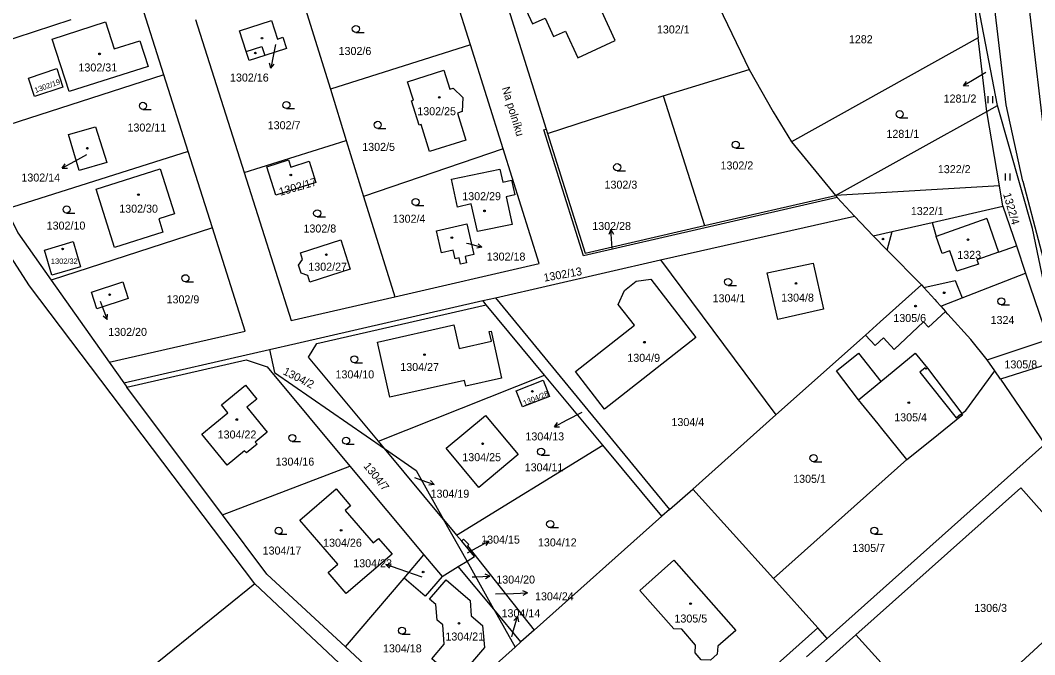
# Model space of a CAD drawing. Extents: x -724107 to -720612, y -1045267 to -1038441.
# Drawn here: x -722495.8 to -722280.4, y -1043826.7 to -1043692 of the extents above; entities that cross this region are included whole.
import ezdxf

# ---------------------------------------------------------------- set-up
doc = ezdxf.new("R2010")
doc.units = 0
for name, color, linetype in [('Hranice parcel', 7, 'Continuous'), ('Parcelní čísla', 7, 'Continuous'), ('Pop  PČ popisy', 7, 'Continuous'), ('Vnitřní kresba', 7, 'Continuous'), ('Značky budov', 7, 'Continuous'), ('Značky kultur', 7, 'Continuous')]:
    doc.layers.add(name, color=color, linetype=linetype)

msp = doc.modelspace()

# ---------------------------------------------------------------- linework, layer by layer
at = {"layer": 'Hranice parcel'}
for p, q in [((-722399.97, -1043664.64), (-722384.11, -1043715.14)), ((-722294.31, -1043678.85), (-722292.37, -1043695.73)), ((-722400.2, -1043697.26), (-722405.73, -1043679.7)), ((-722436.75, -1043684.63), (-722429.94, -1043706.64)), ((-722349.01, -1043685.75), (-722340.98, -1043702.46)), ((-722465.29, -1043703.63), (-722470.49, -1043687.27)), ((-722485.03, -1043691.96), (-722513.89, -1043701.27)), ((-722458.59, -1043691.86), (-722448.26, -1043724.35)), ((-722292.37, -1043695.73), (-722332.05, -1043717.8)), ((-722290.57, -1043711.4), (-722292.37, -1043695.73)), ((-722400.2, -1043697.26), (-722429.94, -1043706.64)), ((-722393.26, -1043719.34), (-722400.2, -1043697.26)), ((-722359.26, -1043708.03), (-722340.98, -1043702.46)), ((-722465.29, -1043703.63), (-722506.29, -1043716.77)), ((-722460.15, -1043719.85), (-722465.29, -1043703.63)), ((-722429.94, -1043706.64), (-722426.56, -1043717.55)), ((-722383.81, -1043716.09), (-722359.26, -1043708.03)), ((-722359.26, -1043708.03), (-722350.49, -1043735.62)), ((-722322.69, -1043729.23), (-722290.57, -1043711.4)), ((-722290.57, -1043711.4), (-722288.3, -1043710.14)), ((-722287.85, -1043727.2), (-722290.57, -1043711.4)), ((-722384.11, -1043715.14), (-722383.81, -1043716.09)), ((-722448.26, -1043724.35), (-722426.56, -1043717.55)), ((-722426.56, -1043717.55), (-722422.87, -1043729.46)), ((-722332.05, -1043717.8), (-722322.69, -1043729.23)), ((-722460.15, -1043719.85), (-722498.76, -1043732.14)), ((-722454.98, -1043736.06), (-722460.15, -1043719.85)), ((-722393.26, -1043719.34), (-722422.87, -1043729.46)), ((-722287.85, -1043727.2), (-722322.69, -1043729.23)), ((-722287.12, -1043731.47), (-722287.85, -1043727.2)), ((-722422.87, -1043729.46), (-722416.28, -1043750.74)), ((-722350.49, -1043735.62), (-722322.69, -1043729.23)), ((-722322.69, -1043729.23), (-722322.3, -1043729.65)), ((-722318.63, -1043733.59), (-722322.3, -1043729.65)), ((-722359.86, -1043742.91), (-722318.63, -1043733.59)), ((-722314.67, -1043737.81), (-722318.63, -1043733.59)), ((-722454.98, -1043736.06), (-722489.2, -1043747.21)), ((-722394.9, -1043750.94), (-722359.86, -1043742.91)), ((-722359.86, -1043742.91), (-722335.35, -1043775.77)), ((-722282.31, -1043745.68), (-722277.54, -1043759.8)), ((-722489.2, -1043747.21), (-722476.9, -1043764.62)), ((-722397.53, -1043751.54), (-722394.9, -1043750.94)), ((-722396.82, -1043752.4), (-722397.53, -1043751.54)), ((-722384.5, -1043767.37), (-722396.82, -1043752.4)), ((-722394.9, -1043750.94), (-722357.94, -1043795.88)), ((-722300.32, -1043752.74), (-722299.29, -1043753.88)), ((-722335.35, -1043775.77), (-722316.32, -1043758.85)), ((-722290.43, -1043764.1), (-722277.54, -1043759.8)), ((-722473.79, -1043769.01), (-722442.89, -1043761.93)), ((-722476.9, -1043764.62), (-722473.79, -1043769.01)), ((-722288.82, -1043766.47), (-722290.43, -1043764.1)), ((-722419.72, -1043781.41), (-722384.5, -1043767.37)), ((-722372.07, -1043782.26), (-722384.5, -1043767.37)), ((-722287.62, -1043768.22), (-722288.82, -1043766.47)), ((-722473.79, -1043769.01), (-722473.14, -1043769.88)), ((-722452.82, -1043797.04), (-722473.14, -1043769.88)), ((-722352.97, -1043791.54), (-722335.35, -1043775.77)), ((-722418.43, -1043782.96), (-722419.72, -1043781.41)), ((-722403.13, -1043801.3), (-722372.07, -1043782.26)), ((-722359.53, -1043797.29), (-722372.07, -1043782.26)), ((-722405.89, -1043798), (-722418.43, -1043782.96)), ((-722452.82, -1043797.04), (-722425.78, -1043786.68)), ((-722425.78, -1043786.68), (-722410.07, -1043805.52)), ((-722335.87, -1043810.55), (-722307.55, -1043785.3)), ((-722357.94, -1043795.88), (-722352.97, -1043791.54)), ((-722352.97, -1043791.54), (-722335.87, -1043810.55)), ((-722405.89, -1043798), (-722403.13, -1043801.3)), ((-722400.92, -1043806.87), (-722405.89, -1043798)), ((-722359.53, -1043797.29), (-722386.68, -1043821.48)), ((-722357.94, -1043795.88), (-722359.53, -1043797.29)), ((-722403.13, -1043801.3), (-722402.04, -1043802.6)), ((-722414.27, -1043810.44), (-722410.07, -1043805.52)), ((-722410.07, -1043805.52), (-722406.23, -1043810.12)), ((-722406.23, -1043810.12), (-722402.77, -1043808)), ((-722402.77, -1043808), (-722400.92, -1043806.87)), ((-722395.23, -1043817.04), (-722402.77, -1043808)), ((-722395.23, -1043817.04), (-722400.92, -1043806.87)), ((-722426.72, -1043825.03), (-722414.27, -1043810.44)), ((-722326.45, -1043821.03), (-722335.87, -1043810.55)), ((-722426.92, -1043829.6), (-722445.95, -1043811.69)), ((-722389.46, -1043823.95), (-722395.23, -1043817.04)), ((-722395.23, -1043817.04), (-722390.73, -1043825.08)), ((-722386.68, -1043821.48), (-722389.46, -1043823.95)), ((-722376.61, -1043865.6), (-722326.45, -1043821.03)), ((-722324.44, -1043823.26), (-722326.45, -1043821.03)), ((-722328.83, -1043827.18), (-722324.44, -1043823.26)), ((-722408.93, -1043841.47), (-722426.72, -1043825.03)), ((-722390.73, -1043825.08), (-722408.93, -1043841.47)), ((-722389.46, -1043823.95), (-722390.73, -1043825.08))]:
    msp.add_line(p, q, dxfattribs=at)
for points in [[(-722389.81, -1043682.03), (-722387.9, -1043686.15), (-722389.71, -1043686.9), (-722386.99, -1043692.79), (-722384.34, -1043691.6), (-722382.56, -1043695.47), (-722380.02, -1043694.33), (-722377.41, -1043699.97), (-722369.45, -1043696.29), (-722378.83, -1043675.95), (-722382.58, -1043668.42), (-722385.33, -1043669.59), (-722392.46, -1043672.62), (-722390.91, -1043676.37), (-722389.81, -1043682.03)], [(-722288.3, -1043710.14), (-722291.19, -1043695.07), (-722294.31, -1043678.85)], [(-722489.03, -1043696.02), (-722477.66, -1043692.38), (-722475.83, -1043698.09), (-722470.41, -1043696.36), (-722468.65, -1043701.83), (-722485.43, -1043707.16), (-722489.03, -1043696.02)], [(-722447.81, -1043698.64), (-722449.2, -1043694.24), (-722442.42, -1043692.09), (-722441.18, -1043696.01), (-722440.03, -1043695.64), (-722439.27, -1043698.03), (-722443.85, -1043699.49), (-722447.2, -1043700.55), (-722447.81, -1043698.64)], [(-722445.95, -1043811.69), (-722493.86, -1043748.42), (-722499.71, -1043739.26), (-722517.12, -1043702.29)], [(-722486.76, -1043706.23), (-722492.79, -1043708.22), (-722494.05, -1043704.29), (-722488.03, -1043702.26), (-722486.76, -1043706.23)], [(-722403.85, -1043706.43), (-722401.79, -1043708.4), (-722401.97, -1043711.4), (-722402.97, -1043711.72), (-722401.16, -1043717.45), (-722408.86, -1043719.89), (-722410.68, -1043714.14), (-722411.07, -1043714.26), (-722412.7, -1043709.12), (-722412.3, -1043708.99), (-722413.54, -1043705.06), (-722405.86, -1043702.62), (-722404.54, -1043706.64), (-722403.85, -1043706.43)], [(-722340.98, -1043702.46), (-722335.9, -1043711.44), (-722332.05, -1043717.8)], [(-722275.1, -1043763.67), (-722280.81, -1043736.21), (-722288.3, -1043710.14)], [(-722477.39, -1043722.2), (-722483.25, -1043723.88), (-722485.57, -1043716.24), (-722479.8, -1043714.65), (-722477.39, -1043722.2)], [(-722322.3, -1043729.65), (-722350.38, -1043736.11), (-722376.19, -1043742.04), (-722384.58, -1043715.29), (-722384.11, -1043715.14)], [(-722383.81, -1043716.09), (-722375.85, -1043741.45), (-722350.49, -1043735.62)], [(-722416.28, -1043750.74), (-722385.6, -1043743.69), (-722393.26, -1043719.34)], [(-722434.44, -1043721.95), (-722433.02, -1043726.43), (-722441.5, -1043729.12), (-722443.41, -1043723.12), (-722438.83, -1043721.67), (-722438.35, -1043723.19), (-722434.44, -1043721.95)], [(-722479.7, -1043727.86), (-722466.08, -1043723.56), (-722463.07, -1043733.1), (-722466.36, -1043734.15), (-722465.49, -1043737.01), (-722475.76, -1043740.27), (-722479.7, -1043727.86)], [(-722448.26, -1043724.35), (-722438.27, -1043755.79), (-722416.28, -1043750.74)], [(-722404.21, -1043725.77), (-722393.98, -1043723.6), (-722393.34, -1043726.39), (-722391.5, -1043725.97), (-722390.74, -1043729.07), (-722392.63, -1043729.51), (-722391.34, -1043735.36), (-722398.71, -1043736.86), (-722400.01, -1043731.01), (-722402.97, -1043731.67), (-722404.21, -1043725.77)], [(-722498.76, -1043732.14), (-722496.3, -1043737.16), (-722489.2, -1043747.21)], [(-722314.67, -1043737.81), (-722310.66, -1043736.89), (-722306.56, -1043735.94), (-722302.18, -1043734.94), (-722287.12, -1043731.47)], [(-722287.12, -1043731.47), (-722284.27, -1043739.9), (-722282.31, -1043745.68)], [(-722406.33, -1043741.37), (-722407.4, -1043736.69), (-722400.97, -1043735.22), (-722399.47, -1043741.75), (-722401.32, -1043742.17), (-722401.01, -1043743.54), (-722402.28, -1043743.83), (-722402.59, -1043742.46), (-722403.47, -1043742.66), (-722403.89, -1043740.81), (-722406.33, -1043741.37)], [(-722476.9, -1043764.62), (-722448.02, -1043758.03), (-722454.98, -1043736.06)], [(-722482.98, -1043744.34), (-722489.07, -1043746.13), (-722490.63, -1043740.82), (-722484.59, -1043738.98), (-722482.98, -1043744.34)], [(-722434.28, -1043747.64), (-722434.74, -1043746.23), (-722436.14, -1043745.72), (-722436.7, -1043744.02), (-722435.85, -1043742.79), (-722436.3, -1043741.38), (-722427.75, -1043738.6), (-722425.7, -1043744.89), (-722434.28, -1043747.64)], [(-722304.4, -1043748.21), (-722311.69, -1043740.83), (-722314.67, -1043737.81)], [(-722327.44, -1043743.57), (-722325.2, -1043753.37), (-722334.92, -1043755.57), (-722337.15, -1043745.65), (-722327.44, -1043743.57)], [(-722300.32, -1043752.74), (-722295.78, -1043750.96), (-722282.31, -1043745.68)], [(-722472.85, -1043751.06), (-722479.52, -1043753.28), (-722480.69, -1043749.75), (-722474.02, -1043747.53), (-722472.85, -1043751.06)], [(-722368.79, -1043752.33), (-722367.51, -1043749.37), (-722365.03, -1043747.38), (-722361.89, -1043746.97), (-722352.3, -1043759.4), (-722371.72, -1043774.58), (-722377.91, -1043766.61), (-722365.35, -1043756.78), (-722368.79, -1043752.33)], [(-722316.32, -1043758.85), (-722313.19, -1043756.06), (-722311.22, -1043754.29), (-722304.4, -1043748.21)], [(-722304.4, -1043748.21), (-722303.93, -1043748.73), (-722301.59, -1043751.33), (-722301.25, -1043751.7), (-722300.32, -1043752.74)], [(-722442.89, -1043761.93), (-722437.26, -1043760.64), (-722397.53, -1043751.54)], [(-722419.72, -1043781.41), (-722434.61, -1043763.57), (-722432.81, -1043760.65), (-722396.82, -1043752.4)], [(-722299.29, -1043753.88), (-722302.93, -1043757.15), (-722303.95, -1043756.01), (-722310.18, -1043761.89), (-722312.46, -1043759.47), (-722314.25, -1043761.09), (-722316.32, -1043758.85)], [(-722290.43, -1043764.1), (-722293.91, -1043759.78), (-722298.79, -1043754.44), (-722299.29, -1043753.88)], [(-722393.58, -1043767.97), (-722401.2, -1043769.7), (-722401.48, -1043768.48), (-722417.31, -1043772.04), (-722419.94, -1043760.35), (-722403.74, -1043756.71), (-722402.6, -1043761.7), (-722395.75, -1043760.14), (-722396.2, -1043758.12), (-722395.82, -1043758.02), (-722393.58, -1043767.97)], [(-722277.54, -1043759.8), (-722276.02, -1043764.56), (-722287.62, -1043768.22)], [(-722442.89, -1043761.93), (-722441.77, -1043766.8), (-722418.43, -1043782.96)], [(-722307.55, -1043785.3), (-722312.8, -1043778.68), (-722313.61, -1043777.7), (-722317.81, -1043772.61), (-722322.46, -1043766.44), (-722317.76, -1043762.71), (-722313.06, -1043768.7), (-722305.78, -1043762.69), (-722303.17, -1043765.87), (-722295.87, -1043775.49)], [(-722473.14, -1043769.88), (-722447.84, -1043764.09), (-722443.38, -1043765.59), (-722425.78, -1043786.68)], [(-722295.87, -1043775.49), (-722295.02, -1043774.86), (-722288.82, -1043766.47)], [(-722447.68, -1043774.16), (-722443.35, -1043779.49), (-722445.89, -1043781.57), (-722445.51, -1043782.04), (-722447.76, -1043783.88), (-722448.14, -1043783.41), (-722451.85, -1043786.45), (-722457.23, -1043779.88), (-722451.7, -1043775.33), (-722453.06, -1043773.68), (-722447.96, -1043769.48), (-722445.55, -1043772.46), (-722447.68, -1043774.16)], [(-722384.74, -1043768.46), (-722383.41, -1043771.87), (-722389.14, -1043774.12), (-722390.45, -1043770.71), (-722384.74, -1043768.46)], [(-722287.62, -1043768.22), (-722278.2, -1043782.03), (-722324.44, -1043823.26)], [(-722405.36, -1043782.87), (-722397.03, -1043775.9), (-722390.05, -1043784.23), (-722398.38, -1043791.21), (-722405.36, -1043782.87)], [(-722307.55, -1043785.3), (-722301.92, -1043780.78), (-722295.89, -1043775.95), (-722295.66, -1043775.76), (-722295.87, -1043775.49)], [(-722418.43, -1043782.96), (-722411.69, -1043787.63), (-722405.89, -1043798)], [(-722430.43, -1043809.24), (-722428.38, -1043807.47), (-722436.43, -1043798.17), (-722428.71, -1043791.53), (-722425.65, -1043795.1), (-722426.78, -1043796.08), (-722420.84, -1043802.99), (-722419.7, -1043802.01), (-722416.82, -1043805.35), (-722426.56, -1043813.71), (-722430.43, -1043809.24)], [(-722267.34, -1043800.47), (-722271.69, -1043804.36), (-722283.34, -1043791.3), (-722318.33, -1043822.49)], [(-722426.72, -1043825.03), (-722443.43, -1043809.58), (-722452.82, -1043797.04)], [(-722402.04, -1043802.6), (-722401.94, -1043802.5), (-722401.67, -1043802.21), (-722400.53, -1043803.28), (-722400.8, -1043803.57), (-722386.68, -1043821.48)], [(-722400.92, -1043806.87), (-722399.31, -1043805.88), (-722402.04, -1043802.6)], [(-722357.03, -1043806.67), (-722343.87, -1043821.55), (-722347.67, -1043824.9), (-722347.8, -1043826.6), (-722349.22, -1043827.88), (-722351.19, -1043827.79), (-722352.46, -1043826.3), (-722352.37, -1043824.66), (-722355.27, -1043821.32), (-722357.01, -1043821.22), (-722364.19, -1043813.05), (-722357.03, -1043806.67)], [(-722406.23, -1043810.12), (-722409.8, -1043814.26), (-722414.27, -1043810.44)], [(-722405.38, -1043810.82), (-722400.26, -1043815.19), (-722400.01, -1043818.46), (-722397.63, -1043820.51), (-722397.22, -1043825.16), (-722403.68, -1043832.66), (-722405.81, -1043830.85), (-722405.92, -1043829.72), (-722408.42, -1043827.57), (-722405.77, -1043824.45), (-722406.09, -1043820.38), (-722407.29, -1043819.35), (-722407.54, -1043816.06), (-722408.88, -1043814.91), (-722405.38, -1043810.82)], [(-722445.95, -1043811.69), (-722477.48, -1043837.14), (-722474.95, -1043859.15)], [(-722266.76, -1043839.14), (-722271.42, -1043834.28), (-722265.86, -1043829.16), (-722274.28, -1043820.01), (-722299.56, -1043843.28), (-722318.33, -1043822.49)], [(-722318.33, -1043822.49), (-722323.78, -1043827.41), (-722326.46, -1043829.83)]]:
    msp.add_lwpolyline(points, dxfattribs=at)
at = {"layer": 'Pop  PČ popisy'}
for p, q in [((-722441.58, -1043697.18), (-722441.99, -1043699.26)), ((-722441.99, -1043699.26), (-722442.56, -1043702.21)), ((-722442.56, -1043702.21), (-722442.86, -1043701.13)), ((-722442.56, -1043702.21), (-722441.88, -1043701.32)), ((-722290.77, -1043703.13), (-722292.89, -1043704.41)), ((-722292.89, -1043704.41), (-722295.46, -1043705.96)), ((-722295.46, -1043705.96), (-722294.86, -1043705.01)), ((-722295.46, -1043705.96), (-722294.35, -1043705.87)), ((-722484.24, -1043721.98), (-722486.86, -1043723.44)), ((-722486.86, -1043723.44), (-722486.23, -1043722.51)), ((-722481.75, -1043720.6), (-722484.24, -1043721.98)), ((-722486.86, -1043723.44), (-722485.75, -1043723.39)), ((-722370.36, -1043736.45), (-722370.79, -1043737.48)), ((-722370.15, -1043739.44), (-722370.36, -1043736.45)), ((-722370.36, -1043736.45), (-722369.79, -1043737.41)), ((-722401, -1043739.33), (-722400.64, -1043739.43)), ((-722400.64, -1043739.43), (-722397.74, -1043740.21)), ((-722397.74, -1043740.21), (-722398.58, -1043739.46)), ((-722370.08, -1043740.39), (-722370.15, -1043739.44)), ((-722397.74, -1043740.21), (-722398.84, -1043740.43)), ((-722478.84, -1043751.65), (-722478.41, -1043752.76)), ((-722478.41, -1043752.76), (-722477.33, -1043755.56)), ((-722477.33, -1043755.56), (-722478.16, -1043754.81)), ((-722477.33, -1043755.56), (-722477.23, -1043754.45)), ((-722376.52, -1043775.27), (-722379.72, -1043776.94)), ((-722379.72, -1043776.94), (-722382.37, -1043778.35)), ((-722382.37, -1043778.35), (-722381.72, -1043777.44)), ((-722382.37, -1043778.35), (-722381.25, -1043778.32)), ((-722412.08, -1043789.12), (-722410.76, -1043789.58)), ((-722410.76, -1043789.58), (-722407.92, -1043790.56)), ((-722407.92, -1043790.56), (-722409.03, -1043790.7)), ((-722407.92, -1043790.56), (-722408.71, -1043789.76)), ((-722400.82, -1043805.07), (-722398.94, -1043804.05)), ((-722398.94, -1043804.05), (-722396.29, -1043802.64)), ((-722396.29, -1043802.64), (-722397.41, -1043802.67)), ((-722396.29, -1043802.64), (-722396.94, -1043803.55)), ((-722418.13, -1043807.53), (-722417.02, -1043807.41)), ((-722415.31, -1043808.56), (-722418.13, -1043807.53)), ((-722418.13, -1043807.53), (-722417.36, -1043808.35)), ((-722410.48, -1043810.27), (-722415.31, -1043808.56)), ((-722399.84, -1043810.2), (-722399.05, -1043810.17)), ((-722399.05, -1043810.17), (-722396.05, -1043810.07)), ((-722396.05, -1043810.07), (-722397.07, -1043809.6)), ((-722396.05, -1043810.07), (-722397.03, -1043810.6)), ((-722394.89, -1043813.8), (-722391.08, -1043813.7)), ((-722391.08, -1043813.7), (-722388.08, -1043813.59)), ((-722388.08, -1043813.59), (-722389.1, -1043813.13)), ((-722388.08, -1043813.59), (-722389.06, -1043814.13)), ((-722391.02, -1043821.51), (-722390.19, -1043818.62)), ((-722390.19, -1043818.62), (-722390.95, -1043819.45)), ((-722390.19, -1043818.62), (-722389.99, -1043819.73)), ((-722391.42, -1043822.9), (-722391.02, -1043821.51))]:
    msp.add_line(p, q, dxfattribs=at)
at = {"layer": 'Vnitřní kresba'}
for p, q in [((-722286.43, -1043710), (-722300.29, -1043591.22)), ((-722277.74, -1043721.43), (-722293.12, -1043591.36)), ((-722447.81, -1043698.64), (-722444.46, -1043697.57)), ((-722444.46, -1043697.57), (-722443.85, -1043699.49)), ((-722282.86, -1043726.17), (-722286.43, -1043710)), ((-722282.86, -1043726.17), (-722275.66, -1043753.66)), ((-722302.18, -1043734.94), (-722301.32, -1043737.92)), ((-722290.55, -1043734.13), (-722301.32, -1043737.92)), ((-722290.55, -1043734.13), (-722288.07, -1043741.24)), ((-722311.69, -1043740.83), (-722310.66, -1043736.89)), ((-722300.03, -1043741.52), (-722301.32, -1043737.92)), ((-722298.38, -1043740.97), (-722300.03, -1043741.52)), ((-722296.93, -1043745.3), (-722298.38, -1043740.97)), ((-722288.07, -1043741.24), (-722292.66, -1043742.87)), ((-722288.07, -1043741.24), (-722284.27, -1043739.9)), ((-722292.34, -1043743.77), (-722296.93, -1043745.3)), ((-722292.66, -1043742.87), (-722292.34, -1043743.77)), ((-722303.93, -1043748.73), (-722297.23, -1043747.27)), ((-722297.23, -1043747.27), (-722295.78, -1043750.96)), ((-722303.63, -1043765.79), (-722304.78, -1043766.74)), ((-722304.78, -1043766.74), (-722297.08, -1043776.44)), ((-722303.4, -1043766.06), (-722303.63, -1043765.79)), ((-722303.17, -1043765.87), (-722303.4, -1043766.06)), ((-722317.81, -1043772.61), (-722313.06, -1043768.7)), ((-722297.08, -1043776.44), (-722296.11, -1043775.67)), ((-722296.11, -1043775.67), (-722295.89, -1043775.95))]:
    msp.add_line(p, q, dxfattribs=at)
at = {"layer": 'Značky budov'}
for centre in [(-722444.46, -1043695.82), (-722445.86, -1043698.97), (-722478.95, -1043699.16), (-722406.8, -1043708.39), (-722481.54, -1043719.19), (-722438.34, -1043724.86), (-722470.69, -1043729.05), (-722397.21, -1043732.49), (-722404.13, -1043738.17), (-722312.6, -1043738.47), (-722294.55, -1043738.61), (-722486.8, -1043740.57), (-722430.79, -1043741.79), (-722331.07, -1043747.9), (-722476.81, -1043750.29), (-722299.58, -1043749.88), (-722305.68, -1043752.71), (-722363.24, -1043760.37), (-722409.95, -1043763), (-722387.04, -1043770.8), (-722307.11, -1043773.22), (-722449.81, -1043776.78), (-722397.6, -1043781.94), (-722427.65, -1043800.32), (-722410.25, -1043809.16), (-722353.46, -1043815.89), (-722402.64, -1043820.05)]:
    msp.add_circle(centre, 0.175, dxfattribs=at)
at = {"layer": 'Značky kultur'}
for p, q in [((-722424.53, -1043694.61), (-722422.78, -1043694.61)), ((-722290.23, -1043709.65), (-722290.23, -1043708.15)), ((-722289.23, -1043709.65), (-722289.23, -1043708.15)), ((-722469.74, -1043710.94), (-722467.99, -1043710.94)), ((-722439.27, -1043710.77), (-722437.52, -1043710.77)), ((-722309.05, -1043712.7), (-722307.3, -1043712.7)), ((-722419.88, -1043714.97), (-722418.13, -1043714.97)), ((-722343.85, -1043719.18), (-722342.1, -1043719.18)), ((-722369.03, -1043723.96), (-722367.28, -1043723.96)), ((-722286.55, -1043726.07), (-722286.55, -1043724.57)), ((-722285.55, -1043726.07), (-722285.55, -1043724.57)), ((-722485.95, -1043732.94), (-722484.2, -1043732.94)), ((-722411.85, -1043731.35), (-722410.1, -1043731.35)), ((-722432.74, -1043733.75), (-722430.99, -1043733.75)), ((-722460.72, -1043747.53), (-722458.97, -1043747.53)), ((-722345.47, -1043748.32), (-722343.72, -1043748.32)), ((-722287.47, -1043752.44), (-722285.72, -1043752.44)), ((-722424.84, -1043764.74), (-722423.09, -1043764.74)), ((-722438.02, -1043781.44), (-722436.27, -1043781.44)), ((-722426.6, -1043782.03), (-722424.85, -1043782.03)), ((-722385.19, -1043784.36), (-722383.44, -1043784.36)), ((-722327.34, -1043785.73), (-722325.59, -1043785.73)), ((-722383.26, -1043799.74), (-722381.51, -1043799.74)), ((-722440.92, -1043801.14), (-722439.17, -1043801.14)), ((-722314.41, -1043801.12), (-722312.66, -1043801.12)), ((-722414.74, -1043822.35), (-722412.99, -1043822.35))]:
    msp.add_line(p, q, dxfattribs=at)
for centre in [(-722424.53, -1043693.86), (-722469.74, -1043710.19), (-722439.27, -1043710.02), (-722309.05, -1043711.95), (-722419.88, -1043714.22), (-722343.85, -1043718.43), (-722369.03, -1043723.21), (-722411.85, -1043730.6), (-722485.95, -1043732.19), (-722432.74, -1043733), (-722460.72, -1043746.78), (-722345.47, -1043747.57), (-722287.47, -1043751.69), (-722424.84, -1043763.99), (-722438.02, -1043780.69), (-722426.6, -1043781.28), (-722385.19, -1043783.61), (-722327.34, -1043784.98), (-722440.92, -1043800.39), (-722383.26, -1043798.99), (-722314.41, -1043800.37), (-722414.74, -1043821.6)]:
    msp.add_circle(centre, 0.75, dxfattribs=at)

# ---------------------------------------------------------------- texts
at = {"layer": 'Parcelní čísla'}
for s, height, p in [('1302/1', 1.7, (-722360.6, -1043694.82)), ('1282', 1.7, (-722319.83, -1043696.9)), ('1302/6', 1.7, (-722428.19, -1043699.39)), ('1302/31', 1.7, (-722483.43, -1043702.89)), ('1302/16', 1.7, (-722451.25, -1043705.03)), ('1281/2', 1.7, (-722299.71, -1043709.49)), ('1302/25', 1.7, (-722411.48, -1043712.18)), ('1302/11', 1.7, (-722473.02, -1043715.64)), ('1302/7', 1.7, (-722443.24, -1043715.15)), ('1281/1', 1.7, (-722311.86, -1043716.98)), ('1302/5', 1.7, (-722423.17, -1043719.75)), ('1302/2', 1.7, (-722347.09, -1043723.69)), ('1302/14', 1.7, (-722495.55, -1043726.26)), ('1322/2', 1.7, (-722300.94, -1043724.48)), ('1302/3', 1.7, (-722371.72, -1043727.77)), ('1302/29', 1.7, (-722401.93, -1043730.22)), ('1302/30', 1.7, (-722474.77, -1043732.87)), ('1302/4', 1.7, (-722416.7, -1043735)), ('1322/1', 1.7, (-722306.68, -1043733.37)), ('1302/10', 1.7, (-722490.18, -1043736.46)), ('1302/8', 1.7, (-722435.65, -1043737.08)), ('1302/28', 1.7, (-722374.32, -1043736.55)), ('1302/18', 1.7, (-722396.74, -1043743.04)), ('1323', 1.7, (-722296.81, -1043742.67)), ('1302/32', 1.139, (-722489.28, -1043743.74)), ('1302/27', 1.7, (-722434.62, -1043745.19)), ('1302/9', 1.7, (-722464.72, -1043752.12)), ('1304/1', 1.7, (-722348.77, -1043751.9)), ('1304/8', 1.7, (-722334.21, -1043751.76)), ('1305/6', 1.7, (-722310.39, -1043756.08)), ('1324', 1.7, (-722289.74, -1043756.51)), ('1302/20', 1.7, (-722477.1, -1043759.03)), ('1304/9', 1.7, (-722366.88, -1043764.53)), ('1304/27', 1.7, (-722415.09, -1043766.48)), ('1305/8', 1.7, (-722286.8, -1043765.93)), ('1304/10', 1.7, (-722428.85, -1043768.05)), ('1304/4', 1.7, (-722357.51, -1043778.17)), ('1305/4', 1.7, (-722310.2, -1043777.17)), ('1304/22', 1.7, (-722453.87, -1043780.81)), ('1304/13', 1.7, (-722388.52, -1043781.22)), ('1304/16', 1.7, (-722441.58, -1043786.57)), ('1304/25', 1.7, (-722401.92, -1043785.63)), ('1304/11', 1.7, (-722388.67, -1043787.78)), ('1305/1', 1.7, (-722331.66, -1043790.22)), ('1304/19', 1.7, (-722408.66, -1043793.38)), ('1304/26', 1.7, (-722431.48, -1043803.79)), ('1304/15', 1.7, (-722397.91, -1043803.12)), ('1304/12', 1.7, (-722385.86, -1043803.72)), ('1304/17', 1.7, (-722444.32, -1043805.45)), ('1305/7', 1.7, (-722319.1, -1043804.89)), ('1304/23', 1.7, (-722425.08, -1043808.15)), ('1304/20', 1.7, (-722394.7, -1043811.61)), ('1304/24', 1.7, (-722386.48, -1043815.17)), ('1304/14', 1.7, (-722393.59, -1043818.76)), ('1306/3', 1.7, (-722293.21, -1043817.63)), ('1305/5', 1.7, (-722356.87, -1043819.88)), ('1304/21', 1.7, (-722405.51, -1043823.7)), ('1304/18', 1.7, (-722418.76, -1043826.22))]:
    msp.add_text(s, height=height, dxfattribs=at).set_placement(p)
for s, height, rotation, p in [('1302/19', 1.139, 20, (-722492.53, -1043707.47)), ('1302/17', 1.7, 16, (-722440.59, -1043729.3)), ('1322/4', 1.7, 286, (-722287.1, -1043728.91)), ('1302/13', 1.7, 10, (-722384.5, -1043747.52)), ('1304/2', 1.7, 333, (-722440.15, -1043767.11)), ('1304/28', 1.139, 23, (-722388.71, -1043773.89)), ('1304/7', 1.7, 309, (-722423, -1043786.72))]:
    msp.add_text(s, height=height, rotation=rotation, dxfattribs=at).set_placement(p)
at = {"layer": 'Pop  PČ popisy'}
msp.add_text('Na polníku', height=1.7, rotation=287, dxfattribs=at).set_placement((-722393.54, -1043706.41))

doc.saveas('drawing.dxf')
